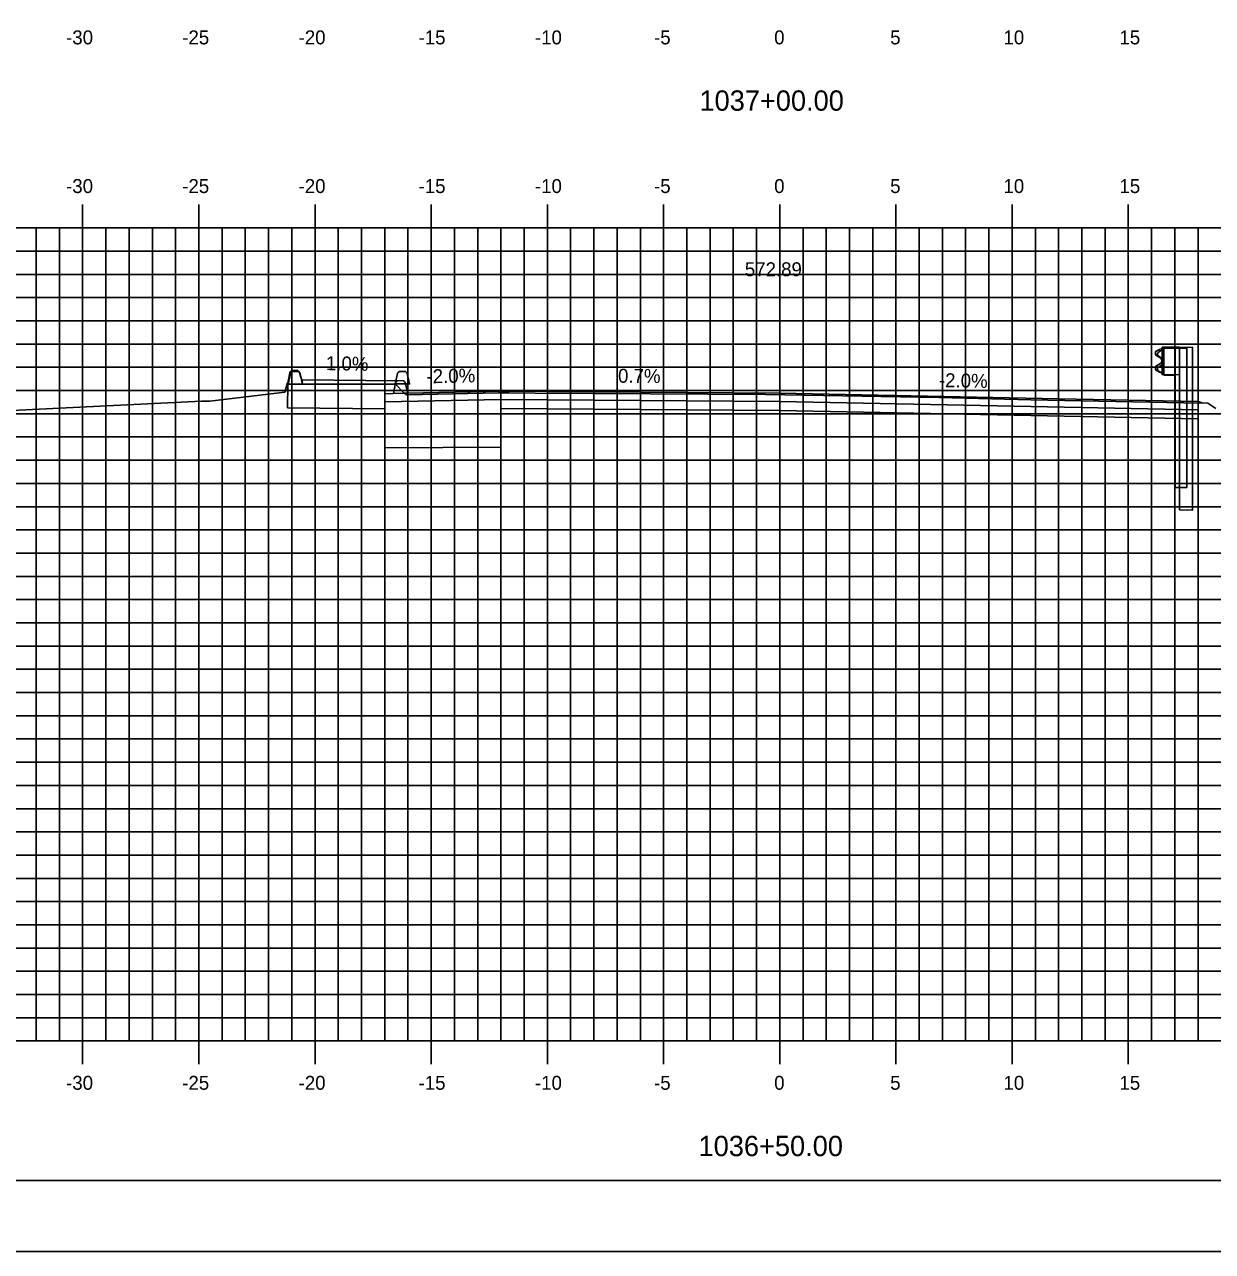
# Model space of a CAD drawing. Extents: x 1060559 to 1060729, y 779716 to 779826.
# Drawn here: x 1060609.6 to 1060660.7, y 779715.6 to 779768.5 of the extents above; entities that cross this region are included whole.
import ezdxf

# ---------------------------------------------------------------- set-up
doc = ezdxf.new("R2010")
doc.units = 0
for name, color, linetype in [('ANNOTATION', 7, 'Continuous'), ('BORDER', 7, 'Continuous'), ('D_Guardrail_Beam_Rt', 7, 'Continuous'), ('D_Roadway_Berm', 7, 'Continuous'), ('D_Roadway_Centerline', 7, 'Continuous'), ('D_Roadway_Centerline_Text', 7, 'Continuous'), ('D_Roadway_Edge_Pavement', 7, 'Continuous'), ('D_Roadway_Edge_Shoulder', 7, 'Continuous'), ('D_Roadway_Pavement', 7, 'Continuous'), ('D_Roadway_Sidewalks_Paved', 7, 'Continuous'), ('D_Roadway_SubGrade', 7, 'Continuous'), ('H_V ANNOTATION', 7, 'Continuous'), ('M_Guardrail', 7, 'Continuous'), ('MAJOR', 7, 'Continuous'), ('MINOR', 7, 'Continuous'), ('PLOT BOUNDARY', 7, 'Continuous'), ('S_Curb_Type_3', 7, 'Continuous'), ('S_Guardrail_Beam', 7, 'Continuous'), ('S_Roadway_Centerline', 7, 'Continuous'), ('S_Roadway_Edge_Pavement', 7, 'Continuous')]:
    doc.layers.add(name, color=color, linetype=linetype)

msp = doc.modelspace()

# ---------------------------------------------------------------- linework, layer by layer
at = {"layer": 'ANNOTATION'}
for p, q in [((1060625.658, 779753.123), (1060621.499, 779753.165)), ((1060625.528, 779752.959), (1060621.543, 779752.999))]:
    msp.add_line(p, q, dxfattribs=at)
msp.add_lwpolyline([(1060625.528, 779752.959), (1060625.455, 779752.573), (1060625.079, 779752.558), (1060625.079, 779752.224)], dxfattribs=at)
at = {"layer": 'BORDER'}
msp.add_lwpolyline([(1060567.08, 779718.706), (1060727.08, 779718.706), (1060727.08, 779823.706), (1060567.08, 779823.706)], close=True, dxfattribs=at)
at = {"layer": 'D_Guardrail_Beam_Rt'}
msp.add_lwpolyline([(1060658.529, 779754.498), (1060658.436, 779754.484), (1060658.418, 779754.478), (1060658.255, 779754.38), (1060658.255, 779754.236), (1060658.476, 779754.097), (1060658.514, 779754.032), (1060658.514, 779753.941), (1060658.476, 779753.877), (1060658.255, 779753.743), (1060658.255, 779753.6), (1060658.418, 779753.498), (1060658.436, 779753.49), (1060658.529, 779753.475)], dxfattribs=at)
for points in [[(1060658.529, 779754.577), (1060659.285, 779754.567), (1060659.285, 779753.386), (1060658.529, 779753.396)], [(1060659.285, 779754.567), (1060659.843, 779754.559), (1060659.843, 779747.559), (1060659.285, 779747.567)]]:
    msp.add_lwpolyline(points, close=True, dxfattribs=at)
at = {"layer": 'D_Roadway_Berm'}
msp.add_lwpolyline([(1060626.079, 779752.597), (1060626.08, 779752.597)], dxfattribs=at)
at = {"layer": 'D_Roadway_Centerline'}
for points in [[(1060621.112, 779753.564), (1060621.288, 779753.571), (1060621.342, 779753.561), (1060621.387, 779753.528), (1060621.413, 779753.479), (1060621.534, 779753.039)], [(1060625.079, 779751.922), (1060620.898, 779751.964), (1060620.908, 779753.013)], [(1060625.658, 779753.123), (1060625.834, 779753.13), (1060625.888, 779753.12), (1060625.933, 779753.087), (1060625.959, 779753.038), (1060626.079, 779752.598)], [(1060625.919, 779752.588), (1060626.069, 779752.598), (1060626.079, 779752.598), (1060626.08, 779752.597), (1060630.079, 779752.678), (1060642.079, 779752.592), (1060654.079, 779752.352), (1060660.079, 779752.232), (1060660.279, 779752.166)], [(1060630.079, 779752.678), (1060630.079, 779752.324), (1060642.079, 779752.239), (1060660.079, 779751.879), (1060660.079, 779752.232)], [(1060630.079, 779752.678), (1060630.079, 779751.928), (1060642.079, 779751.842), (1060660.079, 779751.482), (1060660.079, 779751.879)]]:
    msp.add_lwpolyline(points, dxfattribs=at)
at = {"layer": 'D_Roadway_Edge_Pavement'}
msp.add_lwpolyline([(1060630.079, 779752.678), (1060630.079, 779752.678), (1060642.079, 779752.592), (1060654.079, 779752.352), (1060642.079, 779752.592), (1060642.079, 779752.592)], close=True, dxfattribs=at)
at = {"layer": 'D_Roadway_Edge_Shoulder'}
msp.add_line((1060654.079, 779752.352), (1060660.079, 779752.232), dxfattribs=at)
msp.add_lwpolyline([(1060625.455, 779752.573), (1060626.079, 779752.598), (1060630.079, 779752.678), (1060630.079, 779752.324), (1060625.079, 779752.224)], dxfattribs=at)
msp.add_lwpolyline([(1060630.079, 779752.678), (1060626.079, 779752.598), (1060630.079, 779752.678)], close=True, dxfattribs=at)
at = {"layer": 'D_Roadway_Pavement'}
for p, q in [((1060626.079, 779752.598), (1060630.079, 779752.678)), ((1060630.079, 779752.678), (1060630.079, 779750.261))]:
    msp.add_line(p, q, dxfattribs=at)
msp.add_lwpolyline([(1060630.079, 779752.678), (1060630.079, 779752.678), (1060642.079, 779752.592), (1060642.079, 779752.592)], close=True, dxfattribs=at)
msp.add_lwpolyline([(1060630.079, 779750.261), (1060625.079, 779750.241), (1060625.079, 779752.224)], dxfattribs=at)
at = {"layer": 'D_Roadway_Sidewalks_Paved'}
for points in [[(1060620.982, 779753.4), (1060620.994, 779753.462), (1060621.016, 779753.513), (1060621.058, 779753.549), (1060621.112, 779753.564)], [(1060625.528, 779752.959), (1060625.54, 779753.021), (1060625.562, 779753.072), (1060625.604, 779753.108), (1060625.658, 779753.123)], [(1060626.069, 779752.598), (1060626.079, 779752.597), (1060626.079, 779752.597), (1060626.069, 779752.598)]]:
    msp.add_lwpolyline(points, dxfattribs=at)
at = {"layer": 'D_Roadway_SubGrade'}
for points in [[(1060620.909, 779753.014), (1060620.982, 779753.4)], [(1060626.079, 779752.597), (1060626.079, 779752.597), (1060626.069, 779752.598)]]:
    msp.add_lwpolyline(points, dxfattribs=at)
msp.add_lwpolyline([(1060630.079, 779752.678), (1060630.079, 779752.678), (1060626.095, 779752.598), (1060626.069, 779752.598), (1060626.069, 779752.598), (1060626.079, 779752.597), (1060626.079, 779752.598), (1060630.079, 779752.678), (1060634.079, 779752.649), (1060634.079, 779752.649)], close=True, dxfattribs=at)
at = {"layer": 'M_Guardrail'}
for p, q in [((1060659.1, 779754.532), (1060659.591, 779754.532)), ((1060659.591, 779754.532), (1060659.591, 779748.532)), ((1060659.1, 779748.532), (1060659.1, 779753.366)), ((1060659.1, 779748.532), (1060659.591, 779748.532))]:
    msp.add_line(p, q, dxfattribs=at)
at = {"layer": 'MAJOR'}
for p, q in [((1060612.079, 779760.708), (1060612.079, 779759.706)), ((1060617.079, 779760.708), (1060617.079, 779759.706)), ((1060622.079, 779760.708), (1060622.079, 779759.706)), ((1060627.079, 779760.708), (1060627.079, 779759.706)), ((1060632.079, 779760.708), (1060632.079, 779759.706)), ((1060637.079, 779760.708), (1060637.079, 779759.706)), ((1060642.079, 779760.708), (1060642.079, 779759.706)), ((1060647.079, 779760.708), (1060647.079, 779759.706)), ((1060652.079, 779760.708), (1060652.079, 779759.706)), ((1060657.079, 779760.708), (1060657.079, 779759.706)), ((1060572.079, 779759.706), (1060712.079, 779759.706)), ((1060572.079, 779759.706), (1060712.079, 779759.706)), ((1060612.079, 779724.706), (1060612.079, 779759.706)), ((1060617.079, 779724.706), (1060617.079, 779759.706)), ((1060622.079, 779724.706), (1060622.079, 779759.706)), ((1060627.079, 779724.706), (1060627.079, 779759.706)), ((1060632.079, 779724.706), (1060632.079, 779759.706)), ((1060637.079, 779724.706), (1060637.079, 779759.706)), ((1060642.079, 779724.706), (1060642.079, 779759.706)), ((1060647.079, 779724.706), (1060647.079, 779759.706)), ((1060652.079, 779724.706), (1060652.079, 779759.706)), ((1060657.079, 779724.706), (1060657.079, 779759.706)), ((1060572.079, 779754.706), (1060712.079, 779754.706)), ((1060572.079, 779749.706), (1060712.079, 779749.706)), ((1060572.079, 779744.706), (1060712.079, 779744.706)), ((1060572.079, 779739.706), (1060712.079, 779739.706)), ((1060572.079, 779734.706), (1060712.079, 779734.706)), ((1060572.079, 779729.706), (1060712.079, 779729.706)), ((1060572.079, 779724.706), (1060712.079, 779724.706)), ((1060572.079, 779724.706), (1060712.079, 779724.706)), ((1060612.079, 779723.704), (1060612.079, 779724.706)), ((1060617.079, 779723.704), (1060617.079, 779724.706)), ((1060622.079, 779723.704), (1060622.079, 779724.706)), ((1060627.079, 779723.704), (1060627.079, 779724.706)), ((1060632.079, 779723.704), (1060632.079, 779724.706)), ((1060637.079, 779723.704), (1060637.079, 779724.706)), ((1060642.079, 779723.704), (1060642.079, 779724.706)), ((1060647.079, 779723.704), (1060647.079, 779724.706)), ((1060652.079, 779723.704), (1060652.079, 779724.706)), ((1060657.079, 779723.704), (1060657.079, 779724.706))]:
    msp.add_line(p, q, dxfattribs=at)
at = {"layer": 'MINOR'}
for p, q in [((1060610.079, 779724.706), (1060610.079, 779759.706)), ((1060611.079, 779724.706), (1060611.079, 779759.706)), ((1060613.079, 779724.706), (1060613.079, 779759.706)), ((1060614.079, 779724.706), (1060614.079, 779759.706)), ((1060615.079, 779724.706), (1060615.079, 779759.706)), ((1060616.079, 779724.706), (1060616.079, 779759.706)), ((1060618.079, 779724.706), (1060618.079, 779759.706)), ((1060619.079, 779724.706), (1060619.079, 779759.706)), ((1060620.079, 779724.706), (1060620.079, 779759.706)), ((1060621.079, 779724.706), (1060621.079, 779759.706)), ((1060623.079, 779724.706), (1060623.079, 779759.706)), ((1060624.079, 779724.706), (1060624.079, 779759.706)), ((1060625.079, 779724.706), (1060625.079, 779759.706)), ((1060626.079, 779724.706), (1060626.079, 779759.706)), ((1060628.079, 779724.706), (1060628.079, 779759.706)), ((1060629.079, 779724.706), (1060629.079, 779759.706)), ((1060630.079, 779724.706), (1060630.079, 779759.706)), ((1060631.079, 779724.706), (1060631.079, 779759.706)), ((1060633.079, 779724.706), (1060633.079, 779759.706)), ((1060634.079, 779724.706), (1060634.079, 779759.706)), ((1060635.079, 779724.706), (1060635.079, 779759.706)), ((1060636.079, 779724.706), (1060636.079, 779759.706)), ((1060638.079, 779724.706), (1060638.079, 779759.706)), ((1060639.079, 779724.706), (1060639.079, 779759.706)), ((1060640.079, 779724.706), (1060640.079, 779759.706)), ((1060641.079, 779724.706), (1060641.079, 779759.706)), ((1060643.079, 779724.706), (1060643.079, 779759.706)), ((1060644.079, 779724.706), (1060644.079, 779759.706)), ((1060645.079, 779724.706), (1060645.079, 779759.706)), ((1060646.079, 779724.706), (1060646.079, 779759.706)), ((1060648.079, 779724.706), (1060648.079, 779759.706)), ((1060649.079, 779724.706), (1060649.079, 779759.706)), ((1060650.079, 779724.706), (1060650.079, 779759.706)), ((1060651.079, 779724.706), (1060651.079, 779759.706)), ((1060653.079, 779724.706), (1060653.079, 779759.706)), ((1060654.079, 779724.706), (1060654.079, 779759.706)), ((1060655.079, 779724.706), (1060655.079, 779759.706)), ((1060656.079, 779724.706), (1060656.079, 779759.706)), ((1060658.079, 779724.706), (1060658.079, 779759.706)), ((1060659.079, 779724.706), (1060659.079, 779759.706)), ((1060660.079, 779724.706), (1060660.079, 779759.706)), ((1060572.079, 779758.706), (1060712.079, 779758.706)), ((1060572.079, 779757.706), (1060712.079, 779757.706)), ((1060572.079, 779756.706), (1060712.079, 779756.706)), ((1060572.079, 779755.706), (1060712.079, 779755.706)), ((1060572.079, 779753.706), (1060712.079, 779753.706)), ((1060572.079, 779752.706), (1060712.079, 779752.706)), ((1060572.079, 779751.706), (1060712.079, 779751.706)), ((1060572.079, 779750.706), (1060712.079, 779750.706)), ((1060572.079, 779748.706), (1060712.079, 779748.706)), ((1060572.079, 779747.706), (1060712.079, 779747.706)), ((1060572.079, 779746.706), (1060712.079, 779746.706)), ((1060572.079, 779745.706), (1060712.079, 779745.706)), ((1060572.079, 779743.706), (1060712.079, 779743.706)), ((1060572.079, 779742.706), (1060712.079, 779742.706)), ((1060572.079, 779741.706), (1060712.079, 779741.706)), ((1060572.079, 779740.706), (1060712.079, 779740.706)), ((1060572.079, 779738.706), (1060712.079, 779738.706)), ((1060572.079, 779737.706), (1060712.079, 779737.706)), ((1060572.079, 779736.706), (1060712.079, 779736.706)), ((1060572.079, 779735.706), (1060712.079, 779735.706)), ((1060572.079, 779733.706), (1060712.079, 779733.706)), ((1060572.079, 779732.706), (1060712.079, 779732.706)), ((1060572.079, 779731.706), (1060712.079, 779731.706)), ((1060572.079, 779730.706), (1060712.079, 779730.706)), ((1060572.079, 779728.706), (1060712.079, 779728.706)), ((1060572.079, 779727.706), (1060712.079, 779727.706)), ((1060572.079, 779726.706), (1060712.079, 779726.706)), ((1060572.079, 779725.706), (1060712.079, 779725.706))]:
    msp.add_line(p, q, dxfattribs=at)
at = {"layer": 'PLOT BOUNDARY'}
msp.add_lwpolyline([(1060558.986, 779715.646), (1060728.986, 779715.646), (1060728.986, 779825.646), (1060558.986, 779825.646)], close=True, dxfattribs=at)
at = {"layer": 'S_Curb_Type_3'}
for points in [[(1060621.443, 779753.43), (1060621.546, 779752.986), (1060620.921, 779752.986), (1060621.023, 779753.43)], [(1060621.145, 779753.527), (1060621.321, 779753.527)], [(1060626.049, 779753.432), (1060626.152, 779752.988), (1060625.527, 779752.988), (1060625.629, 779753.432)], [(1060625.751, 779753.529), (1060625.927, 779753.529)]]:
    msp.add_lwpolyline(points, dxfattribs=at)
for centre, start, end in [((1060621.145, 779753.402), 90, 167.0054), ((1060621.321, 779753.402), 12.9946, 90), ((1060625.751, 779753.404), 90, 167.0054), ((1060625.927, 779753.404), 12.9946, 90)]:
    msp.add_arc(centre, 0.125, start, end, dxfattribs=at)
at = {"layer": 'S_Guardrail_Beam'}
for p, q in [((1060658.61, 779754.532), (1060659.1, 779754.532)), ((1060658.61, 779753.366), (1060658.61, 779754.532)), ((1060659.1, 779754.532), (1060659.1, 779753.366)), ((1060658.512, 779754.438), (1060658.368, 779754.338)), ((1060658.368, 779754.195), (1060658.563, 779754.059)), ((1060658.61, 779754.459), (1060658.528, 779754.445)), ((1060658.597, 779753.995), (1060658.597, 779753.903)), ((1060658.563, 779753.839), (1060658.368, 779753.703)), ((1060658.368, 779753.56), (1060658.512, 779753.46)), ((1060658.528, 779753.453), (1060658.61, 779753.439)), ((1060659.1, 779753.366), (1060658.61, 779753.366))]:
    msp.add_line(p, q, dxfattribs=at)
for centre, major_axis, start_param, end_param in [((1060658.418, 779754.267), (-0.0877, 0), 5.323254, 7.243116), ((1060658.535, 779754.404), (-0.0417, 0), 4.886922, 5.323254), ((1060658.518, 779753.995), (0.0789, 0), 0, 0.959931), ((1060658.418, 779753.631), (-0.0877, 0), 5.323254, 7.243116), ((1060658.535, 779753.494), (-0.0417, 0), 0.959931, 1.396263), ((1060658.518, 779753.903), (0.0789, 0), 5.323254, 6.283185)]:
    msp.add_ellipse(centre, major_axis=major_axis, ratio=0.995501, start_param=start_param, end_param=end_param, dxfattribs=at)
at = {"layer": 'S_Roadway_Centerline'}
for points in [[(1060601.472, 779751.475), (1060617.199, 779752.241), (1060617.33, 779752.243), (1060617.422, 779752.25), (1060617.549, 779752.247), (1060620.779, 779752.629), (1060620.896, 779753.041), (1060620.921, 779752.986), (1060624.572, 779752.981), (1060625.527, 779752.988), (1060625.914, 779752.591), (1060626.024, 779752.518), (1060629.971, 779752.601), (1060630.433, 779752.609), (1060631.551, 779752.585), (1060641.471, 779752.538), (1060648.944, 779752.402), (1060652.886, 779752.3), (1060659.465, 779752.178), (1060660.505, 779752.162), (1060660.848, 779751.938)], [(1060641.471, 779752.538), (1060641.471, 779752.538)]]:
    msp.add_lwpolyline(points, dxfattribs=at)
at = {"layer": 'S_Roadway_Edge_Pavement'}
for points in [[(1060626.024, 779752.518), (1060626.024, 779752.518)], [(1060660.505, 779752.162), (1060660.506, 779752.162)]]:
    msp.add_lwpolyline(points, dxfattribs=at)

# ---------------------------------------------------------------- texts
at = {"layer": 'ANNOTATION'}
for s, rotation, p in [('1.0%', 358.8542, (1060622.543, 779753.585)), ('-2.0%', 1.1486, (1060626.883, 779753.014)), ('0.7%', 359.5924, (1060635.118, 779753.042)), ('-2.0%', 358.8542, (1060648.923, 779752.856))]:
    msp.add_text(s, height=0.6, rotation=rotation, dxfattribs=at).set_placement(p)
at = {"layer": 'D_Roadway_Centerline_Text'}
msp.add_text('572.89', height=0.6, dxfattribs=at).set_placement((1060640.576, 779757.624))
at = {"layer": 'H_V ANNOTATION'}
for s, height, p in [('-30', 0.6, (1060611.368, 779767.606)), ('-25', 0.6, (1060616.365, 779767.606)), ('-20', 0.6, (1060621.373, 779767.606)), ('-10', 0.6, (1060631.544, 779767.606)), ('0', 0.6, (1060641.839, 779767.606)), ('10', 0.6, (1060651.705, 779767.606)), ('-15', 0.6, (1060626.536, 779767.606)), ('-5', 0.6, (1060636.67, 779767.606)), ('5', 0.6, (1060646.831, 779767.606)), ('15', 0.6, (1060656.697, 779767.606)), ('1037+00.00', 0.875, (1060638.623, 779764.749)), ('-30', 0.6, (1060611.368, 779761.206)), ('-25', 0.6, (1060616.365, 779761.206)), ('-20', 0.6, (1060621.373, 779761.206)), ('-15', 0.6, (1060626.536, 779761.206)), ('-10', 0.6, (1060631.544, 779761.206)), ('-5', 0.6, (1060636.67, 779761.206)), ('0', 0.6, (1060641.839, 779761.206)), ('5', 0.6, (1060646.831, 779761.206)), ('10', 0.6, (1060651.705, 779761.206)), ('15', 0.6, (1060656.697, 779761.206)), ('-30', 0.6, (1060611.368, 779722.606)), ('-25', 0.6, (1060616.365, 779722.606)), ('-20', 0.6, (1060621.373, 779722.606)), ('-15', 0.6, (1060626.536, 779722.606)), ('-10', 0.6, (1060631.544, 779722.606)), ('-5', 0.6, (1060636.67, 779722.606)), ('0', 0.6, (1060641.839, 779722.606)), ('5', 0.6, (1060646.831, 779722.606)), ('10', 0.6, (1060651.705, 779722.606)), ('15', 0.6, (1060656.697, 779722.606)), ('1036+50.00', 0.875, (1060638.584, 779719.749))]:
    msp.add_text(s, height=height, dxfattribs=at).set_placement(p)
at = {"layer": 'S_Roadway_Centerline'}
for s, p in [('C', (1060641.466, 779752.538)), ('L', (1060641.471, 779752.531))]:
    msp.add_text(s, height=0.0146, dxfattribs=at).set_placement(p)

doc.saveas('drawing.dxf')
